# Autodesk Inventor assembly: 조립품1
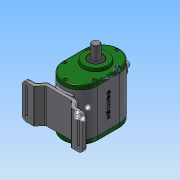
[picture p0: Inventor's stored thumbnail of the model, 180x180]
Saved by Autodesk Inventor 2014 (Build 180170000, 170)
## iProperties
Created: 2018-07
Part Number: 조립품1
Document SubType Name: Assembly
Designer: 학생용
Author: 학생용
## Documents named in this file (14)
- C:\Users\학생용\Desktop\380707V1001\조립품1.iam
- C:\Users\학생용\Desktop\380707V1001\본체.ipt
- C:\Users\학생용\Desktop\380707V1001\메인축.ipt
- C:\Users\학생용\Desktop\380707V1001\서브축.ipt
- C:\Users\학생용\Desktop\380707V1001\베어링 608.ipt
- C:\Users\학생용\Desktop\380707V1001\베어링 6003.ipt
- C:\Users\학생용\Desktop\380707V1001\앞커버.ipt
- C:\Users\학생용\Desktop\380707V1001\오일 실 17 32 8.ipt
- C:\Users\학생용\Desktop\380707V1001\볼트 M4.ipt
- C:\Users\학생용\Desktop\380707V1001\뒤커버.ipt
- C:\Users\학생용\Desktop\380707V1001\오일 실 8 22 7.ipt
- C:\Users\학생용\Desktop\380707V1001\슬라이더.ipt
- C:\Users\학생용\Desktop\380707V1001\가변스프링.ipt
- C:\Users\학생용\Desktop\380707V1001\부시.ipt
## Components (1 placed, 1 different names)
1. 가변스프링:1
